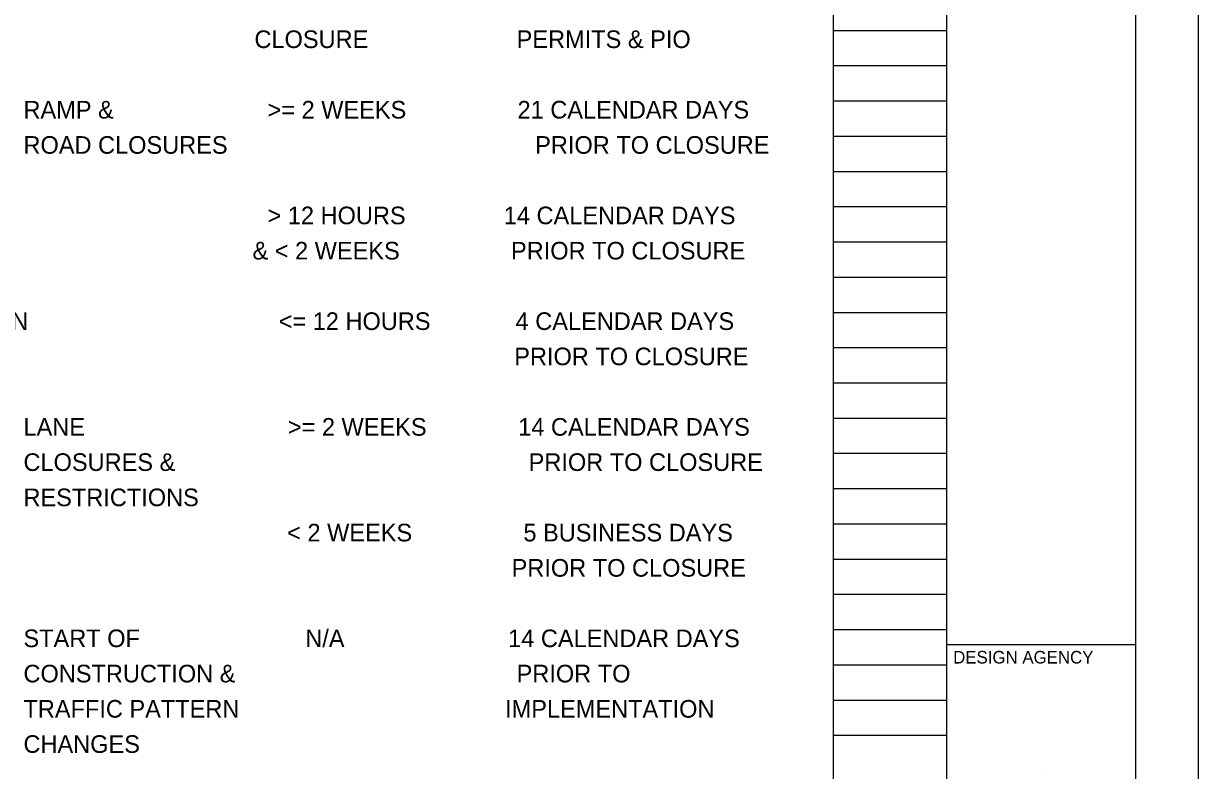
# Model space of a CAD drawing. Extents: x 0 to 63.3, y -2.5 to 22.
# Drawn here: x 24.66 to 34, y 3.5 to 9.43 of the extents above; entities that cross this region are included whole.
import ezdxf

# ---------------------------------------------------------------- set-up
doc = ezdxf.new("R2010")
doc.units = 0
for name, color, linetype in [('SH_Border', 7, 'Continuous'), ('SH_Cut_Line', 7, 'Continuous'), ('SH_Data', 7, 'Continuous'), ('SH_Text', 7, 'Continuous')]:
    doc.layers.add(name, color=color, linetype=linetype)

msp = doc.modelspace()

# ---------------------------------------------------------------- linework, layer by layer
at = {"layer": 'SH_Border'}
for p, q in [((32, 0.5), (32, 21.5)), ((32, 4.5), (33.5, 4.5))]:
    msp.add_line(p, q, dxfattribs=at)
msp.add_lwpolyline([(1.5, 21.5), (33.5, 21.5), (33.5, 0.5), (1.5, 0.5)], close=True, dxfattribs=at)
at = {"layer": 'SH_Cut_Line'}
msp.add_lwpolyline([(0, 0), (34, 0), (34, 22), (0, 22)], close=True, dxfattribs=at)
at = {"layer": 'SH_Data'}
for p, q in [((31.1, 0.98), (31.1, 21.14)), ((32, 0.98), (32, 21.14)), ((31.1, 9.38), (32, 9.38)), ((31.1, 9.1), (32, 9.1)), ((31.1, 8.82), (32, 8.82)), ((31.1, 8.54), (32, 8.54)), ((31.1, 8.26), (32, 8.26)), ((31.1, 7.98), (32, 7.98)), ((31.1, 7.7), (32, 7.7)), ((31.1, 7.42), (32, 7.42)), ((31.1, 7.14), (32, 7.14)), ((31.1, 6.86), (32, 6.86)), ((31.1, 6.58), (32, 6.58)), ((31.1, 6.3), (32, 6.3)), ((31.1, 6.02), (32, 6.02)), ((31.1, 5.74), (32, 5.74)), ((31.1, 5.46), (32, 5.46)), ((31.1, 5.18), (32, 5.18)), ((31.1, 4.9), (32, 4.9)), ((31.1, 4.62), (32, 4.62)), ((31.1, 4.34), (32, 4.34)), ((31.1, 4.06), (32, 4.06)), ((31.1, 3.78), (32, 3.78)), ((32.75, 3.5), (32.75, 3.5))]:
    msp.add_line(p, q, dxfattribs=at)

# ---------------------------------------------------------------- texts
msp.add_text('DESIGN AGENCY', height=0.1, dxfattribs=at).set_placement((32.05, 4.35))
at = {"layer": 'SH_Text'}
for s, p in [('   CLOSURE          ', (26.34, 9.24)), ('PERMITS & PIO', (28.58, 9.24)), ('RAMP &          ', (24.66, 8.68)), ('     >= 2 WEEKS                 21 CALENDAR DAYS', (26.34, 8.68)), ('ROAD CLOSURES                                               PRIOR TO CLOSURE', (24.66, 8.4)), ('     > 12 HOURS               14 CALENDAR DAYS', (26.34, 7.84)), ('                                   & < 2 WEEKS                 PRIOR TO CLOSURE', (24.66, 7.56)), ('PROCESS SHALL BE ADJUSTED TO GRADE OR, IF SUBSTANTIAL DETERIORATION', (17.24, 7)), ('                                       <= 12 HOURS             4 CALENDAR DAYS', (24.66, 7)), ('                                                                           PRIOR TO CLOSURE', (24.66, 6.72)), ('LANE                               >= 2 WEEKS              14 CALENDAR DAYS', (24.66, 6.16)), ('CLOSURES &                                                      PRIOR TO CLOSURE', (24.66, 5.88)), ('RESTRICTIONS', (24.66, 5.6)), ('        < 2 WEEKS                 5 BUSINESS DAYS', (26.34, 5.32)), ('          PRIOR TO CLOSURE', (28.02, 5.04)), ('START OF            ', (24.66, 4.48)), ('N/A                         14 CALENDAR DAYS', (26.9, 4.48)), ('CONSTRUCTION &                  ', (24.66, 4.2)), ('PRIOR TO', (28.58, 4.2)), ('TRAFFIC PATTERN                     ', (24.66, 3.92)), ('         IMPLEMENTATION', (28.02, 3.92)), ('CHANGES', (24.66, 3.64))]:
    msp.add_text(s, height=0.14, dxfattribs=at).set_placement(p)

doc.saveas('drawing.dxf')
